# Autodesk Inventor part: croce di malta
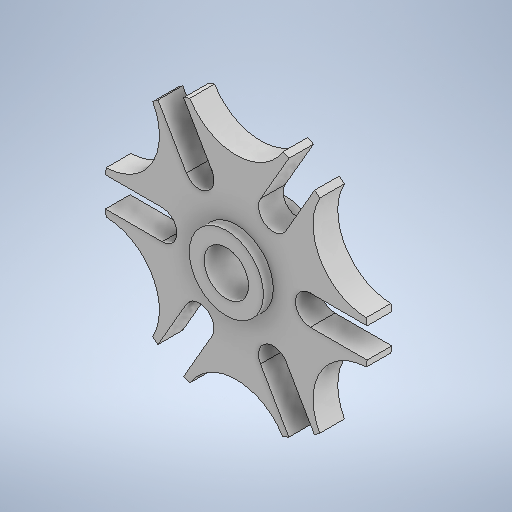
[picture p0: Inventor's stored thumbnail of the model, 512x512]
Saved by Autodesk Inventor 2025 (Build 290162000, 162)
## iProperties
Created: 2025-10
Part Number: croce di malta
Material: Generico
Document SubType Name: Modeling
Designer: 18619647
Density: 1 g/cm^3
Appearance: Default
Author: 18619647
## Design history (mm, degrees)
sketch "Schizzo1"
  geometry: C1 r 80 at (0, 0); 1 further point
  constraints: 1 centre point, 1 coincident
  dimensions: "d0" = 160 diameter of C1
extrude "Estrusione1" new body sketch "Schizzo1" distance "d1" = 15; taper "d2" = 0 deg
sketch "Schizzo2"
  geometry: C1 r 22.5 at (0, 0); 1 further point
  constraints: 1 centre point, 1 coincident
  dimensions: "d3" = 45 diameter of C1
extrude "Estrusione2" join sketch "Schizzo2" distance "d4" = 6; taper "d6" = 0 deg; dims "d5" = 30, "d7" = 0
sketch "Schizzo3"
  geometry: L1 (45, 9)-(86.437, 9); L2 (86.437, 9)-(86.437, -9); L3 (86.437, -9)-(45, -9); C1 r 33 at (0, 92); A1 r 9 centre (45, 0) between (45, 9) and (45, -9); 1 further point
  constraints: 6 end point, 2 centre point, 2 point on circle, 2 tangent, 1 horizontal, 1 perpendicular
  dimensions: "d9" = 66 diameter of C1; "d11" = 18 diameter of A1; "d12" = 18 distance of L1.end L2.end
extrude "Estrusione3" cut sketch "Schizzo3" extent not by distance; stored distance "d13" = 0; taper "d14" = 0 deg
pattern_circular "Serie circolare1" dims angle "d16" = 360 deg
sketch "Schizzo4"
  geometry: C1 r 22.5 at (0, 0) reference; 2 further points
  constraints: 1 coincident
hole "Foro1" sketch "Schizzo4" at (0, 0) diameter "d18" = 27; stored, may be unused: countersink angle "d22" = 90 deg, drill point angle "d24" = 118 deg; dims "d19" = 6, "d20" = 4, "d21" = 2, "d23" = 8
node "Piano di lavoro1"
sketch "Schizzo5"
  geometry: L1 (-67.86, 0)-(-67.86, 15) reference; L2 (-67.86, 15)-(-56.971, 15) reference; L3 (-56.971, 15)-(-56.971, 0) reference; L4 (-56.971, 0)-(-67.86, 0) reference; L5 (56.971, 0)-(56.971, 15) reference; L6 (56.971, 15)-(67.86, 15) reference; L7 (67.86, 15)-(67.86, 0) reference; L8 (67.86, 0)-(56.971, 0) reference; L9 (0, -15)-(0, 0) reference; L10 (29.971, 0)-(0, 0) reference; L11 (29.971, 15)-(29.971, 0) reference; L12 (0, 15)-(29.971, 15) reference; L13 (0, 15)-(0, 21) reference; L14 (0, 0)-(-29.971, 0) reference; L15 (-29.971, 0)-(-29.971, 15) reference; L16 (-29.971, 15)-(0, 15) reference; L17 (0, -15)-(0, -7.5); C1 r 3.25 at (0, -7.5)
  constraints: 2 end point, 1 centre point, 1 coincident, 1 midpoint
  dimensions: "d26" = 7.5 distance of L9.start L17.end; "d27" = 6.5 diameter of C1
extrude "Estrusione4" cut sketch "Schizzo5" extent not by distance; stored distance "d28" = 10; taper "d29" = 0 deg
node "Solido1"
node "Proietta spigoli di taglio1"
other parameters: "d25" = 22.5
